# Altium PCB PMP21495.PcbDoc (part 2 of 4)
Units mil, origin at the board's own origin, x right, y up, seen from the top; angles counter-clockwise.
Board outline 10700 x 5800 mil, 6 copper layers (Top Layer, Signal Layer 3, Signal Layer 1, Signal Layer 2, Signal Layer 4, Bottom Layer), stack 66 mil thick; 305 components, 138 nets, 864 pads, 367 vias.
Unrouted connection lines stored in the file: 2.
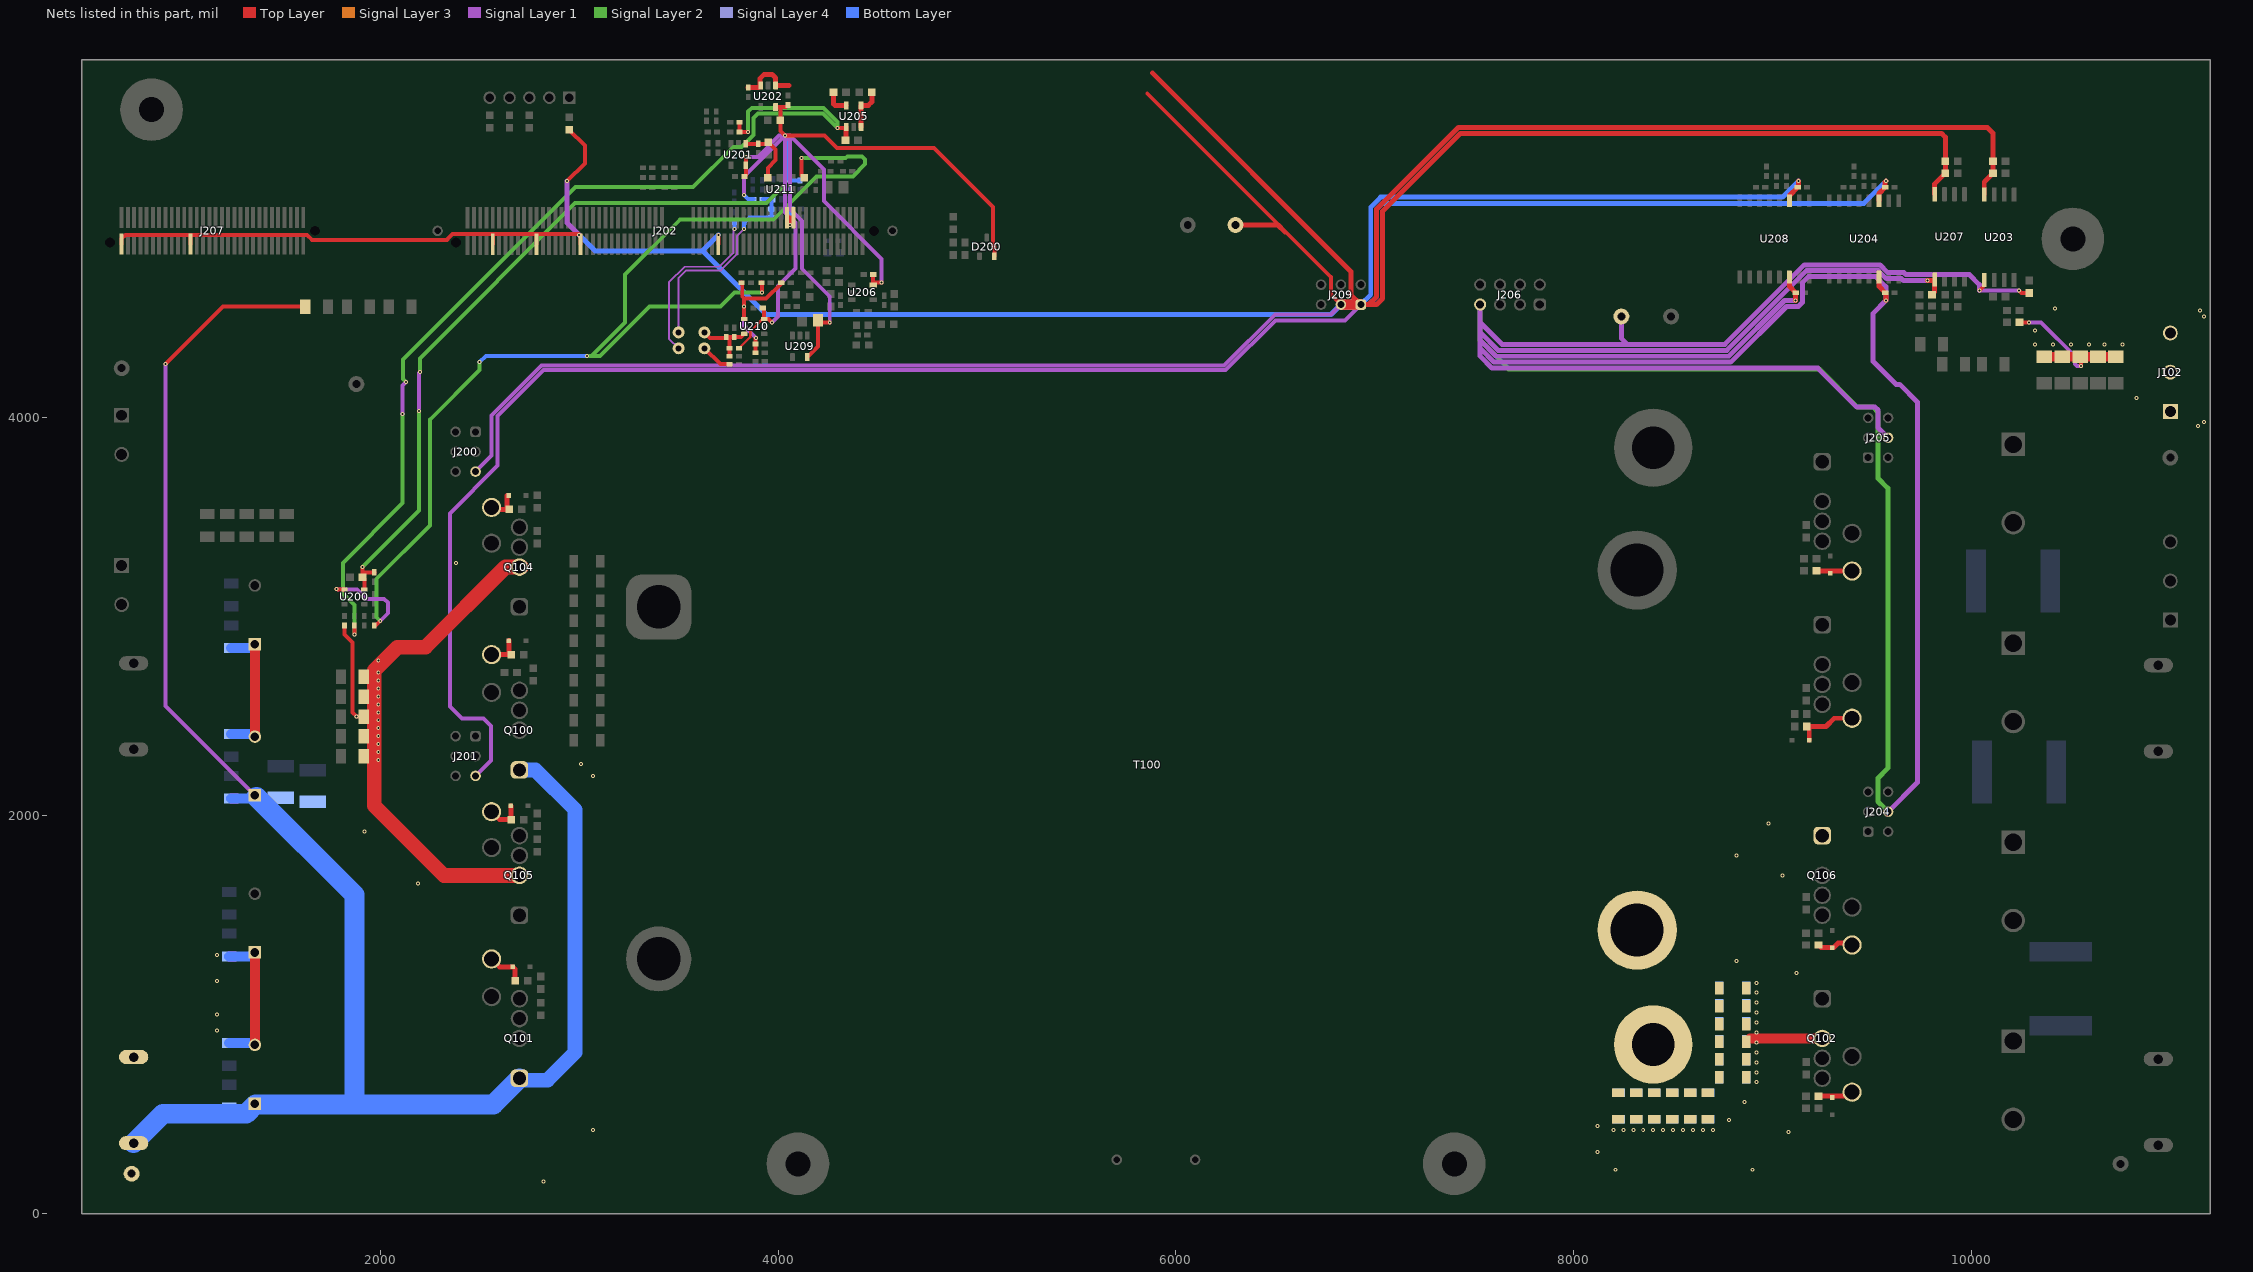
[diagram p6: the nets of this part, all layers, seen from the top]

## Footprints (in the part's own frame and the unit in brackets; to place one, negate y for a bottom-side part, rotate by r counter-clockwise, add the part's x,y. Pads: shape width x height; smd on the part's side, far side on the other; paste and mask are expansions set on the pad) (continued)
0603 [mm] "0603 from SM-752 data"
  rect 1x0.95 smd: 1(-0.8,0) 2(0.8,0)
  silkscreen extent -1.52,-0.69 1.52,0.69, body extent -0.87,-0.47 0.87,0.47, height 1
0805_HV [mil] "0805 with 30mil clearance between pads"
  rect 50x63 smd: 1(-40,0) 2(40,0)
  silkscreen extent -74,-40 74,40, body extent -43,-29 43,29, height 57
1206 [mm] "1206 from SM-752 data"
  rect 1.3x1.85 smd: 1(-1.45,0) 2(1.45,0)
  silkscreen extent -2.4,-1.21 2.4,1.21, body extent -1.7,-0.9 1.7,0.9, height 1.35
1206_190 [mm] "1206_190"
  rect 1.1x1.6 smd: 1(-1.7,0) 2(1.7,0)
  silkscreen extent -0.9,-1 0.9,1, body extent -1.75,-0.95 1.75,0.95, height 1.9
1812_254 [mm] "SMD, 2-Leads, Body 4.8x3.4mm"
  rect 1.6x3.4 smd: 1(-2,0) 2(2,0)
  silkscreen extent -0.8,-1.7 0.8,1.7, body extent -2.4,-1.7 2.4,1.7, height 2.54
B58031I_1084x785x450 [mm] "SMD, 2-Leads, Body 6.84x7.85mm"
  rect 2.5x8 smd: 1(-4.75,0) 2(4.75,0)
  silkscreen extent -3.2,-3.92 3.2,3.93, body extent -5.67,-4.17 5.67,4.18, height 4.5
CAPRD1000W60D900H1200 [mm] "Disk, Radial Capacitor"
  round 1.35 hole 0.85: 1(-5,0) 2(5,0)
  silkscreen extent -5.3,-3.5 5.3,3.5, body extent -4.48,-3.5 4.48,3.5, height 11.99
controlCARD-120HSEC [mm] "Pads are not numbered according to Samtec datasheet."
  rect 0.5x2.724 smd: 1(-23.357,-1.678) 2(-23.357,1.722) 3(-22.557,-1.678) 4(-22.557,1.722) 5(-21.757,-1.678) 6(-21.757,1.722) 7(-20.957,-1.678) 8(-20.957,1.722) 9(-20.157,-1.678) 10(-20.157,1.722) 11(-19.357,-1.678) 12(-19.357,1.722) 13(-18.557,-1.678) 14(-18.557,1.722) 15(-17.757,-1.678) 16(-17.757,1.722) 17(-16.957,-1.678) 18(-16.957,1.722) 19(-16.157,-1.678) 20(-16.157,1.722) 21(-15.357,-1.678) 22(-15.357,1.722) 23(-14.557,-1.678) 24(-14.557,1.722) 25(-13.757,-1.678) 26(-13.757,1.722) 27(-12.957,-1.678) 28(-12.957,1.722) 29(-12.157,-1.678) 30(-12.157,1.722) 31(-11.357,-1.678) 32(-11.357,1.722) 33(-10.557,-1.678) 34(-10.557,1.722) 35(-9.757,-1.678) 36(-9.757,1.722) 37(-8.957,-1.678) 38(-8.957,1.722) 39(-8.157,-1.678) 40(-8.157,1.722) 41(-7.357,-1.678) 42(-7.357,1.722) 43(-6.557,-1.678) 44(-6.557,1.722) 45(-5.757,-1.678) 46(-5.757,1.722) 47(-4.957,-1.678) 48(-4.957,1.722) 49(-4.157,-1.678) 50(-4.157,1.722) 51(-3.357,-1.678) 52(-3.357,1.722) 53(-2.557,-1.678) 54(-2.557,1.722) 55(-1.757,-1.678) 56(-1.757,1.722) 57(2.243,-1.678) 58(2.243,1.722) 59(3.043,-1.678) 60(3.043,1.722) 61(3.843,-1.678) 62(3.843,1.722) 63(4.643,-1.678) 64(4.643,1.722) 65(5.443,-1.678) 66(5.443,1.722) 67(6.243,-1.678) 68(6.243,1.722) 69(7.043,-1.678) 70(7.043,1.722) 71(7.843,-1.678) 72(7.843,1.722) 73(8.643,-1.678) 74(8.643,1.722) 75(9.443,-1.678) 76(9.443,1.722) 77(10.243,-1.678) 78(10.243,1.722) 79(11.043,-1.678) 80(11.043,1.722) 81(11.843,-1.678) 82(11.843,1.722) 83(12.643,-1.678) 84(12.643,1.722) 85(13.443,-1.678) 86(13.443,1.722) 87(14.243,-1.678) 88(14.243,1.722) 89(15.043,-1.678) 90(15.043,1.722) 91(15.843,-1.678) 92(15.843,1.722) 93(16.643,-1.678) 94(16.643,1.722) 95(17.443,-1.678) 96(17.443,1.722) 97(18.243,-1.678) 98(18.243,1.722) 99(19.043,-1.678) 100(19.043,1.722) 101(19.843,-1.678) 102(19.843,1.722) 103(20.643,-1.678) 104(20.643,1.722) 105(21.443,-1.678) 106(21.443,1.722) 107(22.243,-1.678) 108(22.243,1.722) 109(23.043,-1.678) 110(23.043,1.722) 111(23.843,-1.678) 112(23.843,1.722) 113(24.643,-1.678) 114(24.643,1.722) 115(25.443,-1.678) 116(25.443,1.722) 117(26.243,-1.678) 118(26.243,1.722) 119(27.043,-1.678) 120(27.043,1.722)
  round 0.025 hole 1.27 unplated mask+0.876: 181(-24.857,0.022) 182(28.543,1.522)
  round 1.348 hole 0.84: 185(-27.207,0.022) 186(30.893,0.022)
  silkscreen extent -32.11,-3.86 35.8,3.9, body extent -31.75,-3.48 35.3,3.52, height 12.35
controlCARD-180HSEC-60pinAddon [mm] "Pads are not numbered according to datasheet."
  round 0.025 hole 1.27 unplated mask+0.876: 61(-13.1,0) 62(13.1,1.5)
  rect 0.5x2.724 smd: 121(-11.6,-1.7) 122(-11.6,1.7) 123(-10.8,-1.7) 124(-10.8,1.7) 125(-10,-1.7) 126(-10,1.7) 127(-9.2,-1.7) 128(-9.2,1.7) 129(-8.4,-1.7) 130(-8.4,1.7) 131(-7.6,-1.7) 132(-7.6,1.7) 133(-6.8,-1.7) 134(-6.8,1.7) 135(-6,-1.7) 136(-6,1.7) 137(-5.2,-1.7) 138(-5.2,1.7) 139(-4.4,-1.7) 140(-4.4,1.7) 141(-3.6,-1.7) 142(-3.6,1.7) 143(-2.8,-1.7) 144(-2.8,1.7) 145(-2,-1.7) 146(-2,1.7) 147(-1.2,-1.7) 148(-1.2,1.7) 149(-0.4,-1.7) 150(-0.4,1.7) 151(0.4,-1.7) 152(0.4,1.7) 153(1.2,-1.7) 154(1.2,1.7) 155(2,-1.7) 156(2,1.7) 157(2.8,-1.7) 158(2.8,1.7) 159(3.6,-1.7) 160(3.6,1.7) 161(4.4,-1.7) 162(4.4,1.7) 163(5.2,-1.7) 164(5.2,1.7) 165(6,-1.7) 166(6,1.7) 167(6.8,-1.7) 168(6.8,1.7) 169(7.6,-1.7) 170(7.6,1.7) 171(8.4,-1.7) 172(8.4,1.7) 173(9.2,-1.7) 174(9.2,1.7) 175(10,-1.7) 176(10,1.7) 177(10.8,-1.7) 178(10.8,1.7) 179(11.6,-1.7) 180(11.6,1.7)
  silkscreen extent -14.68,-3.88 14.68,3.88, body extent -14.3,-3.5 14.3,3.5, height 7.95
CSNL1206 [mm] "Stackpole Electronics"
  rrect6% 1.6x2 smd: 1(-1.7,0) 2(1.7,0)
  silkscreen extent -0.63,-1.02 0.63,1.05, body extent -1.72,-0.92 1.72,0.92, height 0.9
DBV0005A_N [mm] "SOT23, 5-Leads, Body 2.9x1.6mm, Pitch 0.95mm, Lead Span 2.8mm, IPC Medium Density"
  rrect17% 1x0.6 smd: 1(-1.375,0.95) 2(-1.375,0) 3(-1.375,-0.95) 4(1.375,-0.95) 5(1.375,0.95)
  silkscreen extent -0.25,-1.55 0.25,1.55, body extent -1.42,-1.46 1.42,1.46, height 1.09
DBV0006A_L [mm] "SOT23, 6-Leads, Body 2.9x1.6mm, Pitch 0.95mm, Lead Span 2.8mm, IPC High Density"
  rrect18% 0.8x0.55 smd: 1(-1.275,0.95) 2(-1.275,0) 3(-1.275,-0.95) 4(1.275,-0.95) 5(1.275,0) 6(1.275,0.95)
  silkscreen extent -1.55,-1.53 0.55,1.53, body extent -1.42,-1.46 1.42,1.46, height 1.12
DDC0005A_N [mm]
  rrect17% 1x0.6 smd: 1(-1.375,0.95) 2(-1.375,0) 3(-1.375,-0.95) 4(1.375,-0.95) 5(1.375,0.95)
  silkscreen extent -1.25,-1.52 0.88,1.57, body extent -1.41,-1.45 1.41,1.45, height 1.1
DW0016B_HV [mm] "High voltage version of DW0016B"
  rrect17% 1.65x0.6 smd: 1(-4.875,4.445) 2(-4.875,3.175) 3(-4.875,1.905) 4(-4.875,0.635) 5(-4.875,-0.635) 6(-4.875,-1.905) 7(-4.875,-3.175) 8(-4.875,-4.445) 9(4.875,-4.445) 10(4.875,-3.175) 11(4.875,-1.905) 12(4.875,-0.635) 13(4.875,0.635) 14(4.875,1.905) 15(4.875,3.175) 16(4.875,4.445)
  silkscreen extent -5.43,-5.25 3,5.25, body extent -5.14,-5.13 5.14,5.13, height 2.5
DWV0008A [mm] "SOIC, 8-Leads, Body 5.95x7.6mm (max), Pitch 1.27mm"
  rrect17% 1.8x0.6 smd: 1(-5.45,1.905) 2(-5.45,0.635) 3(-5.45,-0.635) 4(-5.45,-1.905) 5(5.45,-1.905) 6(5.45,-0.635) 7(5.45,0.635) 8(5.45,1.905)
  silkscreen extent -6.25,-2.95 2.98,2.95, body extent -5.77,-2.92 5.77,2.93, height 2.67
Eaton_1A3400-10 [mm] "TH, 2-Leads, Body 11.1x11.94mm"
  oval 1.8x3.75 hole 1.2 slot 2.5 at 90 deg: 1(-5.5,0) 2(5.5,0)
  body extent -5.85,-6.41 5.85,6.41, height 18.03
FC_1600x4000 [mm] "TH, 2-Leads, Dia 16mm, Pin Spacing 7.5mm"
  rect 1.6x1.6 hole 1.1: 1(-3.75,0)
  round 1.6 hole 1.1: 2(3.75,0)
  silkscreen extent -8.25,-8.25 8.25,8.25, body extent -8.19,-8.24 8.23,8.24, height 42.01
FCC_disclaimer [mil]
IEC_HighVoltage_Medium [mil]
  silkscreen extent -217,-176 217,200
IEC_HotSurface_Medium [mil]
  silkscreen extent -217,-188 217,188
Keystone5000 [mil] "For Keystone 500x miniature loop terminals"
  round 80 hole 40: 1(0,0)
  silkscreen extent -52,-52 52,52, body extent -49,-49 49,49, height 182
Keystone5001 [mil] "For Keystone 500x miniature loop terminals"
  round 80 hole 40: 1(0,0)
  silkscreen extent -52,-52 52,52, body extent -49,-49 49,49, height 182
Keystone_575-4#1 [mm] "Banana Jack"
  round 10 hole 5.45: 1(0,-1.27)
  body extent -3.95,-3.95 3.92,3.93, height 2.36
Keystone_575-4#2 [mm] "Banana Jack"
  round 10 hole 5.45: 1(0,2.54)
  body extent -3.95,-3.95 3.92,3.93, height 2.36
Keystone_1902C [mil] "Hex Standoff, 4-40 threaded, nylon"
  round 1 on Mech3: 0(0,0)
  body extent -145,-126 146,126, height 501
Mill-Max_0312-0-15-15-34-27-10-0 [mm] "Pin Receptacle, .032-.046\" .075\" Dia, Gold, TH"
  round 2.45 hole 1.905: 1(0,0)
  silkscreen extent -1.52,-1.52 1.52,1.52, body extent -1.15,-1.15 1.16,1.15, height 0.46
Nichicon_2200x4500_Snap [mm]
  rrect3% 3x3 hole 2.2: 1(-5,0)
  round 3 hole 2.2: 2(5,0)
  silkscreen extent -11.6,-11.6 11.6,11.6, body extent -11.5,-11.49 11.51,11.49, height 47.01
"NY PMS 440 0025 PH" [mm] "4-40 nylon screw and mounting hole"
  round 8 hole 3.2: 1(0,0)
  body extent -3.3,-3.3 3.3,3.3, height 2.69
Payton_60518 [mm] "TH, 4-Leads, Body 130x90mm"
  rrect50% 8.325x8.325 hole 5.55: 1(-66.474,18.288)
  round 8.325 hole 5.55: 3(-66.474,-26.67)
  round 10.125 hole 6.75: 4(58.48,-22.985) 8(58.48,22.985)
  body extent -82.97,-45 65,45, height 60
Pb-Free_Overlay_Medium [mil]
  silkscreen extent -95,-95 95,95
Samtec_SSW-104-24-x-D [mm] "Receptacle, 2.54mm, 4x2, TH"
  rrect50% 1.55x1.55 hole 1.04: 1(-3.81,1.27)
  round 1.55 hole 1.04: 2(-3.81,-1.27) 3(-1.27,1.27) 4(-1.27,-1.27) 5(1.27,1.27) 6(1.27,-1.27) 7(3.81,1.27) 8(3.81,-1.27)
  silkscreen extent -5.43,-2.58 5.43,3, body extent -5.33,-2.48 5.33,2.48, height 8.51
SOD-323 [mm] "NXP recommended land pattern"
  rect 0.6x0.6 smd paste-0.05: 1(-1.1,0) 2(1.1,0)
  silkscreen extent -2.06,-0.86 1.53,0.86, body extent -1.3,-0.67 1.3,0.68, height 1.1
SOT-23 [mm] "SOT23, 3-Leads, Body 2.9x1.3mm, Pitch 0.95mm, Lead Span 2.5mm, IPC Medium Density"
  rrect50% 1x0.6 smd: 1(-1.2,0.95) 2(-1.2,-0.95) 3(1.2,0)
  silkscreen extent -1.62,-1.5 0.7,1.5, body extent -1.16,-1.45 1.21,1.45, height 1
TE_215307-3 [mm] "Receptacle, 2.54mm, 3x2, TH"
  rrect50% 1.35x1.35 hole 0.9: 1(-2.54,1.27)
  round 1.35 hole 0.9: 2(-2.54,-1.27) 3(0,1.27) 4(0,-1.27) 5(2.54,1.27) 6(2.54,-1.27)
  body extent -3.81,-2.53 3.81,2.53, height 7
TE_282856-2 [mm] "TH, 2-Leads, Body 10x10mm, Pitch 5mm"
  rect 1.9x1.9 hole 1.4: 1(-2.5,0)
  round 1.9 hole 1.4: 2(2.5,0)
  silkscreen extent -5.61,-5 5.5,5, body extent -5,-5 5.5,5, height 19
TE_282856-3 [mm] "Receptacle, 3x1, 5mm, R/A, TH"
  rect 1.9x1.9 hole 1.4: 1(-5,0)
  round 1.9 hole 1.4: 2(0,0) 3(5,0)
  silkscreen extent -8,-5 8,5, body extent -7.5,-5 8,5, height 19
TO-247-4 [mm] "FM, 4-Leads, Body 15.94x5.02mm, Pitch 2.54mm"
  rrect50% 2.24x2.24 hole 1.7: 1(-5.08,0)
  round 2.24 hole 1.7: 2(0,0) 3(2.54,0) 4(5.08,0)
  silkscreen extent -8.07,-2.49 8.07,2.72, body extent -8.07,-2.49 8.07,2.72, height 27.97
WEEE_Minimum [mil] "WEEElie bin"
  silkscreen extent -95,-172 99,104
Wurth_61300511021 [mm] "Header, 2.54 mm, 5x1, R/A, TH"
  rect 1.6x1.6 hole 1.1: 1(-5.08,0)
  round 1.6 hole 1.1: 2(-2.54,0) 3(0,0) 4(2.54,0) 5(5.08,0)
  silkscreen extent -6.75,-4.04 6.35,-1.5, body extent -6.35,-10.04 6.35,0.32, height 2.55

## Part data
C100 C105 C108 C109 C110 C113 C114 C115 C116 C117 C118 C119 C120 C121 C122 C123 C124 C125 C126 C127 C128 C129 C134 C135 C136 C137 C138 C139 C140 C141 C146 C147 C148 C149: library part CMP-0008795-2, "CAP CER 8200PF 630V NP0 1206", Cap_Case=1206, Manufacturer=TDK, PartNumber=CGA5L4NP02J822J160AA, TempCo=C0G, Tolerance_%=5%, Value1=Unknown, Value2=630V, ValueDisplayed=8200pF
C101 C102 C111 C112: library part EEU-FC2A471, "CAP ALUM 150UF 20% 400V RADIAL", Cap_Case=16x40mm, Manufacturer=Rubycon, Tolerance_%=20, Value2=400V, ValueDisplayed=150µF
C103 C104 C106 C107: library part LLS2G221MELZ, "CAP ALUM 150UF 20% 500V SNAP", Cap_Case=22x45mm, Manufacturer=Rubycon, Tolerance_%=20, Value2=500V, ValueDisplayed=150µF
C130: library part C1812W104KDRACTU, "CAP, CERM, 0.1 µF, 1000 V,+/- 10%, X7R, 1812", Cap_Case=1812, Manufacturer="Knowles Syfer", TempCo=X7R, Tolerance_%=10, Value2=1000V, ValueDisplayed=0.1µF
C131: library part C1812W104KDRACTU, "CAP CER 0.1UF 1KV X7R 1812", Cap_Case=1812, Manufacturer="Knowles Syfer", TempCo=X7R, Tolerance_%=10, Value2=1000V, ValueDisplayed=0.1µF
C132 C133 C142: library part CMP-0009311-2, "CAP, CERM, 1 uF, 500 V, +/- 20%, B58031, AEC-Q200 Grade 0, 6.84x7.85mm", Cap_Case=10.84x7.85x4.5mm, Manufacturer=TDK, Supplier Part Number 1=495-6707-ND, TempCo=B58031, Tolerance_%=20%, Value1=Unknown, Value2=500V, ValueDisplayed=1uF
C158: "CAP, CERM, 2200 pF, 250 V, +/- 20%, E, Cap, 7x12x9 mm", Cap_Case=CAPRD1000W60D900H1200, Manufacturer=MuRata, Supplier Part Number 1=490-7047-ND, TempCo=E, Tolerance_%=20, Value1=Unknown, Value2=250V, ValueDisplayed=2200pF
C200: "CAP CER 2200PF 6.3V X7R 0402", Cap_Case=0402, Manufacturer=MuRata, Supplier Part Number 1=GRM155R60J222KA01D-ND, TempCo=X5R, Tolerance_%=10, Value2=6.3V, ValueDisplayed=2200pF
C201 C211 C225 C227 C230 C231: library part 06033C104JAT2A, "CAP, CERM, 0.1uF, 25V, +/-5%, X7R, 0603", Cap_Case=0603, Manufacturer=MuRata, Supplier Part Number 1=490-8015-1-ND, TempCo=X7R, Tolerance_%=10, Value2=16V, ValueDisplayed=0.1µF
C202 C205 C240: "CAP, CERM, 0.1uF, 25V, +/-5%, X7R, 0603", Cap_Case=0603, Manufacturer=AVX, Supplier Part Number 1=478-3713-1-ND, TempCo=X7R, Tolerance_%=5, Value1="0.05 ohm", Value2=25V, ValueDisplayed=0.1µF
C203 C206 C207: "CAP, CERM, 470 pF, 50 V,+/- 10%, X7R, AEC-Q200 Grade 1, 0402", Cap_Case=0402, Manufacturer=TDK, Supplier Part Number 1=445-6888-1-ND, TempCo=X7R, Tolerance_%=10, Value1="4.96489 ohm", Value2=50V, ValueDisplayed=470pF
C204: "CAP, CERM, 10 pF, 50 V,+/- 5%, C0G/NP0, 0603", Cap_Case=0603, Manufacturer=Kemet, Supplier Part Number 1=399-1049-1-ND, TempCo=C0G/NP0, Tolerance_%=5, Value2=50V, ValueDisplayed=10pF
C208 C216 C217 C221 C229 C232: "CAP, CERM, 0.01 µF, 10 V,+/- 10%, X5R, 0402", Cap_Case=0402, Manufacturer=MuRata, Supplier Part Number 1=GRM155R61A103KA01D-ND, TempCo=X5R, Tolerance_%=10, Value2=10V, ValueDisplayed=0.01µF
C209 C218 C223: "CAP, CERM, 1uF, 25V, +/-10%, X7R, 0603", Cap_Case=0603, Manufacturer=TDK, Supplier Part Number 1=445-5956-1-ND, TempCo=X7R, Tolerance_%=10, Value1=Unknown, Value2=25V, ValueDisplayed=1uF
C210 C224: "CAP, CERM, 4.7 µF, 10 V,+/- 10%, X5R, 0603", Cap_Case=0603, Manufacturer=TDK, Supplier Part Number 1=445-7482-1-ND, TempCo=X5R, Tolerance_%=10, Value2=10V, ValueDisplayed=4.7µF
C212 C213 C214 C219 C226 C233 C241: "CAP, CERM, 0.1 µF, 25 V,+/- 20%, X7R, 0402", Cap_Case=0402, Manufacturer=TDK, Supplier Part Number 1=445-7349-1-ND, TempCo=X7R, Tolerance_%=20, Value2=25V, ValueDisplayed=0.1µF
C215 C228: "CAP, CERM, 0.01 µF, 100 V,+/- 10%, X7R, 0603", Cap_Case=0603, Manufacturer=AVX, Supplier Part Number 1=478-1205-1-ND, TempCo=X7R, Tolerance_%=10, Value1="0.098 ohm", Value2=100V, ValueDisplayed=0.01µF
C220 C222: "CAP, CERM, 0.1uF, 6.3V, +/-10%, X7R, 0402", Cap_Case=0402, Manufacturer=MuRata, Supplier Part Number 1=GRM155R70J104KA01D-ND, TempCo=X7R, Tolerance_%=10, Value1=Unknown, Value2=6.3V, ValueDisplayed=0.1uF
C234 C235 C236 C237: library part CMP-0085851-1, "CAP, CERM, 22 pF, 50 V,+/- 5%, C0G/NP0, 0402", Cap_Case=0402, Manufacturer=MuRata, Supplier Part Number 1=490-8589-1-ND, TempCo=C0G/NP0, Tolerance_%=1, Value2=50V, ValueDisplayed=22pF
C238: "CAP, CERM, 2.2 µF, 6.3 V,+/- 10%, X6S, 0603", Cap_Case=0603, Manufacturer=MuRata, Supplier Part Number 1=GRM188C80J225KE19D-ND, TempCo=X6S, Tolerance_%=10, Value2=6.3V, ValueDisplayed=2.2µF
C239: "CAP, CERM, 220 pF, 50 V,+/- 5%, C0G/NP0, 0402", Cap_Case=0402, Manufacturer=MuRata, Supplier Part Number 1=490-1293-1-ND, TempCo=C0G/NP0, Tolerance_%=5, Value2=50V, ValueDisplayed=220pF
C242 C244 C245 C254: "CAP, CERM, 10 pF, 10 V,+/- 2.5%, C0G/NP0, 0402", Cap_Case=0402, Manufacturer=Kemet, Supplier Part Number 1=399-8939-1-ND, TempCo=C0G/NP0, Tolerance_%=2.5, Value2=10V, ValueDisplayed=10pF
C243: "CAP, CERM, 0.1 µF, 25 V,+/- 5%, X7R, 0805", Cap_Case=0805, Manufacturer=AVX, Supplier Part Number 1=478-7946-1-ND, TempCo=X7R, Tolerance_%=5, Value2=25V, ValueDisplayed=0.1µF
C246 C250: "CAP, CERM, 2.2 pF, 50 V,+/- 5%, C0G/NP0, 0402", Cap_Case=0402, Manufacturer=MuRata, Supplier Part Number 1=490-6227-1-ND, TempCo=C0G/NP0, Tolerance_%=5, Value2=50V, ValueDisplayed=2.2pF
C247 C249 C251 C253: "CAP, CERM, 0.1 µF, 16 V,+/- 10%, X7R, 0402", Cap_Case=0402, Manufacturer=AVX, Supplier Part Number 1=478-7888-1-ND, TempCo=X7R, Tolerance_%=10, Value2=16V, ValueDisplayed=0.1µF
C248 C252: "CAP, CERM, 2200 pF, 50 V,+/- 10%, X7R, AEC-Q200 Grade 1, 0402", Cap_Case=0402, Manufacturer=TDK, Supplier Part Number 1=445-5606-1-ND, TempCo=X7R, Tolerance_%=10, Value1="1.07794 ohm", Value2=50V, ValueDisplayed=2200pF
D100 D101 D102 D103 D104 D105 D106 D107: "Diode, Schottky, 40 V, 0.5 A, SOD-323", Manufacturer=Toshiba, Supplier Part Number 1=CUS05S40H3FCT-ND, Value1=0.5A, Value2=0.6V
D200: library part CMP-0028456-1, "Diode, Schottky, 30 V, 0.2 A, SOT-23", Manufacturer="Diodes Inc.", Supplier Part Number 1=BAT54S-FDICT-ND, Value1=0.2A, Value2=0.65V
H200 H201 H202 H203: library part CMP-0003617-1, "Machine Screw, Round, #4-40 x 1/4, Nylon, Philips panhead", Manufacturer="B&F Fastener Supply", Supplier Part Number 1=H542-ND
H204 H205 H206 H207: library part CMP-0003610-1, "Standoff, Hex, 0.5\"L #4-40 Nylon", Manufacturer=Keystone, Supplier Part Number 1=36-1902C-ND
J100 J103: library part CMP-0054978-1, "Therminal Block, 5 mm, 2-pole, Tin, TH", Manufacturer="TE Connectivity", Supplier Part Number 1=A98355-ND
J101 J102: library part CMP-0054983-1, "Receptacle, 3x1, 5mm, R/A, TH", Color=Green, Current_A=24A, Manufacturer="TE Connectivity", Supplier Part Number 1=A98356-ND, Voltage_V=300V
J104 J105: library part CMP-0055165-2, "Standard Banana Jack, Uninsulated, 5.5mm", Manufacturer=Keystone, Supplier Part Number 1=36-575-4-ND
J200 J201 J204 J205 J209: library part CMP-0082603-1, "Receptacle, 2.54mm, 3x2, Tin, TH", Color=Green, Manufacturer="TE Connectivity", Supplier Part Number 1=A106656-ND
J202: library part controlCARD-120HSEC, "C2000 controlCARD-120HSEC connector, SMT", Manufacturer=Samtec
J203: library part CMP-0054800-1, "Header, 2.54 mm, 5x1, Gold, R/A, TH", Color=Black, Manufacturer="Wurth Elektronik", Supplier Part Number 1=732-5338-ND
J206: library part CMP-0055706-1, "Receptacle, 2.54mm, 4x2, Gold, TH", Color=Black, Current_A=4.7A, Manufacturer=Samtec, Voltage_V=465V
J207: library part CMP-0003859-2, "C2000 controlCARD-180HSEC (60-pin addon) connector, SMT", Manufacturer=Samtec
Logo2: library part CMP-0074839-1
Logo3: library part CMP-0074847-1, "FCC_disclaimer"
Logo4: library part CMP-0074769-1
LOGO100: library part IEC_HotSurface, "IEC 61010-1 Hot Surface Warning"
LOGO101 LOGO102 LOGO104: library part IEC_HighVoltage, "IEC 61010-1 High Voltage Warning"
Q100 Q101 Q102 Q103 Q104 Q105 Q106 Q107: library part CMP-0067575-2, "ZFET 900V, 30 MOHM, G3 SIC MOSFE", Alternate Manufacturer=None, Manufacturer=Cree
R100 R101 R105 R106 R110 R111 R114 R115: "RES, 1.00 M, 1%, 0.25 W, 1206", Manufacturer=Vishay-Dale, Power_W=0.25, Supplier Part Number 1=541-1.00MFCT-ND, TempCo="100 ppm/C", Tolerance_%=1, Value1=1%, Value2=0.25W, Value_Code=1M00, ValueDisplayed=1.00M
R102 R104 R108 R112 R116: library part CSNL1206FT5L00, "RES 0.006 OHM 1% 1W 1206", Manufacturer="Vishay Dale", Power_W=1, TempCo="50 ppm/C", Value1=1%, Value2=1W, ValueDisplayed=0.006
R103 R107 R109 R113 R117 R142 R143 R144 R145 R146: library part CMP-0018570-2, "RES, 0.01, 1%, 1 W, 1206", Manufacturer=Vishay-Dale, Power_W=1W, Supplier Part Number 1=WSLP-.01CT-ND, TempCo="75 ppm/C", Tolerance_%=1%, Value_Code=R010, ValueDisplayed=0.01
R118 R119 R120 R121 R130 R131 R132 R133: "RES, 5.11, 1%, 0.1 W, 0603", Manufacturer=Vishay-Dale, Power_W=0.1, Supplier Part Number 1=541-5.11HHCT-ND, TempCo="100 ppm/C", Tolerance_%=1, Value1=1%, Value2=0.1W, Value_Code=5R11, ValueDisplayed=5.11
R122 R123 R124 R125 R134 R135 R136 R137: "RES, 1.00, 1%, 0.1 W, 0603", Manufacturer="Yageo America", Power_W=0.1, Supplier Part Number 1=311-1.00HRCT-ND, TempCo="200 ppm/C", Tolerance_%=1, Value1=1%, Value2=0.1W, Value_Code=1R00, ValueDisplayed=1.00
R126 R127 R128 R129 R138 R139 R140 R141: "RES, 10.0 k, 1%, 0.1 W, 0603", Manufacturer=Vishay-Dale, Power_W=0.1, Supplier Part Number 1=541-10.0KHCT-ND, TempCo="100 ppm/C", Tolerance_%=1, Value1=1%, Value2=0.1W, Value_Code=10k0, ValueDisplayed=10.0k
R200 R201 R219 R220: "RES, 0, 5%, 0.063 W, 0402", Manufacturer=Vishay-Dale, Power_W=0.063, Supplier Part Number 1=541-0.0JCT-ND, TempCo="200 ppm/C", Tolerance_%=5, Value1=5%, Value2=0.063W, Value_Code=0000, ValueDisplayed=0
R202 R205 R210: library part CMP-0016927-3, "RES, 365 k, 1%, 0.25 W, AEC-Q200 Grade 0, 1206", Manufacturer=Vishay-Dale, Power_W=250mW, Supplier Part Number 1=541-365KFCT-ND, TempCo="100 ppm/C", Tolerance_%=1%, Value2=0.25W, Value_Code=365k
R203 R207 R229 R253 R254 R264: "RES SMD 56.2 OHM 1% 1/16W 0402", Manufacturer=Vishay-Dale, Power_W=0.063, Supplier Part Number 1=541-56.2LCT-ND, TempCo="100 ppm/C", Tolerance_%=1, Value1=1%, Value2=0.063W, Value_Code=56R2, ValueDisplayed=56.2
R204 R215: library part CRCW0402150KFKED, "RES, 150 k, 1%, 0.063 W, 0402", Manufacturer=Panasonic, Power_W=100mW, Supplier Part Number 1=P240KLCT-ND, TempCo="100 ppm/C", Tolerance_%=1%, Value2=0.1W, Value_Code=240k
R206: "RES, 28.7 k, 1%, 0.125 W, 0805", Manufacturer=Vishay-Dale, Power_W=0.125, Supplier Part Number 1=541-28.7KCCT-ND, TempCo="100 ppm/C", Tolerance_%=1, Value1=1%, Value2=0.125W, Value_Code=28k7, ValueDisplayed=28.7k
R208 R213 R216 R217 R256 R259 R261 R265: "RES, 10.0 k, 1%, 0.063 W, 0402", Manufacturer=Vishay-Dale, Power_W=0.063, Supplier Part Number 1=541-10.0KLCT-ND, TempCo="100 ppm/C", Tolerance_%=1, Value1=1%, Value2=0.063W, Value_Code=10k0, ValueDisplayed=10.0k
R209 R218: library part CMP-0022243-4, "RES, 25.5, 1%, 0.1 W, AEC-Q200 Grade 0, 0603", Manufacturer=Vishay-Dale, Power_W=100mW, Supplier Part Number 1=541-25.5HCT-ND, TempCo="100 ppm/C", Tolerance_%=1%, Value2=0.1W, Value_Code=25R5, ValueDisplayed=25.5
R211: "RES, 1.24 k, 1%, 0.063 W, 0402", Manufacturer=Vishay-Dale, Power_W=0.063, Supplier Part Number 1=541-1.24KLCT-ND, TempCo="100 ppm/C", Tolerance_%=1, Value1=1%, Value2=0.063W, Value_Code=1k24, ValueDisplayed=1.24k
R212: "RES, 56.2, 1%, 0.1 W, 0603", Manufacturer=Vishay-Dale, Power_W=0.1, Supplier Part Number 1=541-56.2HCT-ND, TempCo="100 ppm/C", Tolerance_%=1, Value1=1%, Value2=0.1W, Value_Code=56R2, ValueDisplayed=56.2
R214: library part CMP-0022512-4, "RES, 5.49 k, 1%, 0.1 W, AEC-Q200 Grade 0, 0603", Manufacturer=Vishay-Dale, Power_W=100mW, Supplier Part Number 1=541-5.49KHCT-ND, TempCo="100 ppm/C", Tolerance_%=1%, Value2=0.1W, Value_Code=5k49, ValueDisplayed=5.49k
R221 R222: "RES, 4.99 k, 1%, 0.063 W, 0402", Manufacturer=Vishay-Dale, Power_W=0.063, Supplier Part Number 1=541-4.99KLCT-ND, TempCo="100 ppm/C", Tolerance_%=1, Value1=1%, Value2=0.063W, Value_Code=4k99, ValueDisplayed=4.99k
R223 R224: "RES, 9.31 k, 1%, 0.063 W, 0402", Manufacturer=Vishay-Dale, Power_W=0.063, Supplier Part Number 1=541-9.31KLCT-ND, TempCo="100 ppm/C", Tolerance_%=1, Value1=1%, Value2=0.063W, Value_Code=9k31, ValueDisplayed=9.31k
R225: library part CMP-0022599-4, "RES, 7.15 k, 1%, 0.1 W, AEC-Q200 Grade 0, 0603", Manufacturer=Vishay-Dale, Power_W=100mW, Supplier Part Number 1=541-7.15KHCT-ND, TempCo="100 ppm/C", Tolerance_%=1%, Value2=0.1W, Value_Code=7k15, ValueDisplayed=7.15k
R226: "RES, 14.3 k, 1%, 0.1 W, 0603", Manufacturer=Vishay-Dale, Power_W=0.1, Supplier Part Number 1=541-14.3KHCT-ND, TempCo="100 ppm/C", Tolerance_%=1, Value1=1%, Value2=0.1W, Value_Code=14k3, ValueDisplayed=14.3k
R227: "RES, 1.00 k, 1%, 0.1 W, 0603", Manufacturer=Vishay-Dale, Power_W=0.1, Supplier Part Number 1=541-1.00KHCT-ND, TempCo="100 ppm/C", Tolerance_%=1, Value1=1%, Value2=0.1W, Value_Code=1k00, ValueDisplayed=1.00k
R228: "RES, 25.5, 1%, 0.1 W, 0603", Manufacturer=Vishay-Dale, Power_W=0.1, Supplier Part Number 1=541-25.5HCT-ND, TempCo="100 ppm/C", Tolerance_%=1, Value1=1%, Value2=0.1W, Value_Code=25R5, ValueDisplayed=25.5
R230 R235: "RES, 39.2, 1%, 0.1 W, 0603", Manufacturer=Vishay-Dale, Power_W=0.1, Supplier Part Number 1=541-39.2HCT-ND, TempCo="100 ppm/C", Tolerance_%=1, Value1=1%, Value2=0.1W, Value_Code=39R2, ValueDisplayed=39.2
R231 R232 R233 R234: library part CMP-0026739-1, "RES, 4.70 k, 1%, 0.0625 W, 0402", Manufacturer="TE Connectivity", Power_W=0.063, Supplier Part Number 1=A121542CT-ND, TempCo="100 ppm/C", Tolerance_%=1, Value1=1%, Value2=0.063W, Value_Code=4k70, ValueDisplayed=4.70k
R236: "RES, 7.15 k, 1%, 0.063 W, 0402", Manufacturer=Vishay-Dale, Power_W=0.063, Supplier Part Number 1=541-7.15KLCT-ND, TempCo="100 ppm/C", Tolerance_%=1, Value1=1%, Value2=0.063W, Value_Code=7k15, ValueDisplayed=7.15k
R237 R239 R240: "RES, 2.00 M, 1%, 0.25 W, 1206", Manufacturer="Yageo America", Power_W=0.25, Supplier Part Number 1=311-2.00MFRCT-ND, TempCo="100 ppm/C", Tolerance_%=1, Value1=1%, Value2=0.25W, Value_Code=2M00, ValueDisplayed=2.00M
R238 R248: library part CMP-0022635-4, "RES, 8.25 k, 1%, 0.1 W, AEC-Q200 Grade 0, 0603", Manufacturer=Vishay-Dale, Power_W=100mW, Supplier Part Number 1=541-8.25KHCT-ND, TempCo="100 ppm/C", Tolerance_%=1%, Value2=0.1W, Value_Code=8k25, ValueDisplayed=8.25k
R241 R247 R249 R250 R251 R252: "RES, 0, 5%, 0.1 W, 0603", Manufacturer=Vishay-Dale, Power_W=0.1, Supplier Part Number 1=541-0.0GCT-ND, TempCo="200 ppm/C", Tolerance_%=5, Value1=5%, Value2=0.1W, Value_Code=0000, ValueDisplayed=0
R242 R243 R244 R245: library part CMP-0022278-4, "RES, 2.55 k, 1%, 0.1 W, AEC-Q200 Grade 0, 0603", Manufacturer=Vishay-Dale, Power_W=100mW, Supplier Part Number 1=541-2.55KHCT-ND, TempCo="100 ppm/C", Tolerance_%=1%, Value2=0.1W, Value_Code=2k55, ValueDisplayed=2.55k
R246: library part CMP-0022242-4, "RES, 25.5 k, 1%, 0.1 W, AEC-Q200 Grade 0, 0603", Manufacturer=Vishay-Dale, Power_W=100mW, Supplier Part Number 1=541-25.5KHCT-ND, TempCo="100 ppm/C", Tolerance_%=1%, Value2=0.1W, Value_Code=25k5, ValueDisplayed=25.5k
R255 R260: "RES, 3.65 k, 1%, 0.063 W, 0402", Manufacturer=Vishay-Dale, Power_W=0.063, Supplier Part Number 1=541-3.65KLCT-ND, TempCo="100 ppm/C", Tolerance_%=1, Value1=1%, Value2=0.063W, Value_Code=3k65, ValueDisplayed=3.65k
R257 R262: "RES, 1.00 k, 1%, 0.063 W, 0402", Manufacturer=Vishay-Dale, Power_W=0.063, Supplier Part Number 1=541-1.00KLCT-ND, TempCo="100 ppm/C", Tolerance_%=1, Value1=1%, Value2=0.063W, Value_Code=1k00, ValueDisplayed=1.00k
R258 R263: library part CRCW04021K00FKED, "RES, 1.00 k, 1%, 0.063 W, 0402", Manufacturer=Vishay-Dale, Power_W=0.063, Supplier Part Number 1=541-10.0KLCT-ND, TempCo="100 ppm/C", Tolerance_%=1, Value1=1%, Value2=0.063W, Value_Code=10k0, ValueDisplayed=10.0k
T100: library part CMP-0081898-1, "Transformer, 25 uH, TH", Manufacturer=Payton, ValueDisplayed=25µH
TP100 TP101 TP109: "Test Point, Miniature, Red, TH", Color=Red, Manufacturer=Keystone, Supplier Part Number 1=36-5000-ND
TP102 TP103 TP105 TP106 TP107: "Test Point, Miniature, Black, TH", Color=Black, Manufacturer=Keystone, Supplier Part Number 1=36-5001-ND
TP108: library part 5000, "Test Point, Miniature, Red, TH", Color=Black, Manufacturer=Keystone, Supplier Part Number 1=36-5001-ND
TP200 TP201 TP202 TP203 TP204 TP205 TP206 TP207 TP208 TP209 TP210 TP211 TP212 TP213 TP214 TP215: library part 0312-0-15-15-34-27-10-0, "Pin Receptacle, .032-.046\" .075\" Dia, Gold, TH", Manufacturer=Mill-Max, Supplier Part Number 1=0312-015153427100-ND
U200 U210 U211: library part CMP-0040149-1, "IC OPAMP VFB 45MHZ RRO SOT23-5", Manufacturer="Texas Instruments", PartNumber=LMV116MF
U201 U206 U209: library part CMP-0040888-1, "Precision, 20 MHz, 0.9 pA Ib, RRIO, CMOS Operational Amplifier, 1.8 to 5.5 V, -40 to 125 degC, 5-pin SOT23 (DBV5), Green (RoHS & no Sb/Br)", Manufacturer="Texas Instruments", Total Supply Voltage(Max)(+5V is 5, +/-5V is 10)=5.5, Total Supply Voltage(Min)(+5V is 5, +/-5V is 10)=1.8
U202: "Capacitor-Free, 150-mA, Low-Dropout Regulator with Foldback Current Limit for Portable Devices, DBV0005A", Alternate Manufacturer="Texas Instruments"
U203: library part CMP-0080587-1, "Precision Reinforced Isolated Amplifier for Current Sensing, DWV0008A (SOIC-8)", Alternate Manufacturer="Texas Instruments"
U204 U208: library part CMP-0076069-2, "High-Immunity, 5.7kVRMS Reinforced Dual-Channel 2/0 Digital Isolator, 100Mbps, DW0016B (SOIC-16)", Alternate Manufacturer="Texas Instruments", Alternate PartNumber=ISO7820FDW
U205: library part CMP-0066190-1, "Low-Drift, Low-Power, Dual-Output VREF and VREF/2 Voltage Reference, DDC0005A (SOT-23-T-5)", Alternate Manufacturer="Texas Instruments", Alternate PartNumber=REF2033AIDDCT
U207: library part CMP-0078341-1, "Precision, 2-V Input, Reinforced Isolated Amplifier, DWV0008A (SOIC-8)", Alternate Manufacturer="Texas Instruments", Alternate PartNumber=AMC1311BDWV
XF100 XF101 XF102 XF103: library part CMP-0082116-2, "FUSE CLIP CARTRIDGE 30A PCB", Manufacturer=Eaton, Supplier Part Number 1=1A3400-10-ND

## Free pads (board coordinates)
  round 60 hole 30: 1(3630,4350) 2(3630,4430) 3(3500,4350) 4(3500,4430)

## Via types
v1: diameter 20, hole 10, Top Layer to Bottom Layer, 367 vias

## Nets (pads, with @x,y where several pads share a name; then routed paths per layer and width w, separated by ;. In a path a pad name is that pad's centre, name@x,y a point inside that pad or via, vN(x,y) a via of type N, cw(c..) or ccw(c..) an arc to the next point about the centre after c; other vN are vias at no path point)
1V65: C217.2 C231.1 R215.1 R236.1 U205.1 | length 5183.6
  Top Layer w20: v1(1870,2910) R215.1@1870,2956.38 ; C217.2@3806.49,5487.13 R236.1@3806.49,5437.13 v1(3850,5437.13) ; v1(4300,5457.13) U205.1@4336.73,5457.13
  Top Layer w25: C231.1@4342.6,5401.22 U205.1@4342.6,5462.99
  Signal Layer 1 w20: v1(2112.13,4020) 2112.13,4162.13 v1(2130,4180)
  Signal Layer 2 w20: v1(1870,2910) 1870,3059.98 1823.17,3106.81 1823.17,3107.41 1812.13,3118.45 1812.13,3271.55 2112.13,3571.55 v1(2112.13,4020) ; v1(2130,4180) 2114.87,4195.13 2114.87,4294.06 2980.81,5160 3572.87,5160 3774.85,5361.98 3816.85,5361.98 3877.72,5422.84 3877.72,5507.72 3900,5530 4227.13,5530 v1(4300,5457.13) 4300,5488.45 4229.2,5559.25 3867.92,5559.25 3850,5541.33 v1(3850,5437.13)
3V3: C201.1 C212.1 C218.2 C220.1 C226.1 C243.1 C247.1 C251.1 D200.2 R208.2 R256.2 R261.2 U200.6 U201.5 U202.5 U206.5 U209.5 U210.6 U211.6 | length 10128
  Top Layer w12: R256.2@3803.62,4350 3860,4406.38 3860,4434.86 3922.54,4497.4 U210.6@3930.2,4497.4
  Top Layer w20: C201.1@1910,3201.5 v1(1910,3250) ; 1912.13,3223.62 R208.2@1970,3223.62 ; U200.6@1920.2,3137.4 C201.1@1920.2,3191.3 ; C212.1@3838.35,5221.66 U201.5@3838.35,5270.12 v1(3838.35,5312.76) ; C247.1@3930.2,4546.3 U210.6@3930.2,4497.4 3952.6,4497.4 v1(3970,4480) ; U202.5@3987.4,5562.99 4039.49,5562.99 C220.1@4050,5573.5 ; 4011.5,5561.04 C218.2@4011.5,5497.13 4011.5,5443.22 v1(4035.59,5419.12) 4232.61,5419.12 4295.59,5356.14 4783.86,5356.14 5080,5060 5080,4870 5087.4,4862.6 D200.2@5087.4,4812.76 ; U209.5@4147.4,4305.87 4200,4358.46 C243.1@4200,4490 ; C243.1@4210,4480 v1(4260,4480) ; C226.1@4478.54,4720.47 4478.54,4680 v1(4520,4680)
  Signal Layer 1 w20: v1(2193.88,4033.88) 2193.88,4225.83 v1(2199.03,4230.97) ; v1(3830,5120) 3830,5213.53 v1(4035.59,5419.12) ; v1(3838.35,5312.76) 3898.97,5312.76 4005.33,5419.12 v1(4035.59,5419.12) ; v1(3970,4480) 4000.02,4510.02 4000.02,4664.27 4087.87,4752.13 4087.87,4981.55 4035.59,5033.83 v1(4035.59,5419.12) ; v1(4260,4480) 4260,4610 4120,4750 4120,4990 4060,5050 4060,5394.71 v1(4035.59,5419.12) ; v1(4520,4680) 4520,4800 4230,5090 4230,5250 4060.88,5419.12 v1(4035.59,5419.12)
  Signal Layer 2 w20: v1(1910,3250) 2193.88,3533.88 v1(2193.88,4033.88) ; v1(2199.03,4230.97) 2199.03,4299.38 2979.65,5080 3941.74,5080 4035.59,5173.85 v1(4035.59,5419.12)
  Bottom Layer w20: v1(3830,5120) 3850,5100 R261.2@3876.38,5100 ; v1(4035.59,5419.12) 4051.85,5402.86 U211.6@4051.85,5200.2 4058.43,5193.62 C251.1@4110,5193.62
3V3ref: C230.1 U205.5 | length 125.6
  Top Layer w25: C230.1@4278.5,5637.13 4278.5,5578.62 4285.87,5571.26 U205.5@4342.6,5571.26
5Vp: C210.1 C211.1 C213.1 C219.1 C222.1 C224.1 C225.1 C227.1 J200.5 J201.5 J202.48 J202.84 J202.98 J202.112 J207.158 J207.180 J209.1 J209.3 R252.2 TP109.1 U202.1 U202.3 U203.8 U204.3 U205.3 U205.4 U207.8 U208.3 | length 37336.4
  Top Layer w20: J207.180@699.57,4874.05 699.57,4901.3 718.27,4920 1632.36,4920 1656.65,4895.71 2335.71,4895.71 2337.79,4897.79 2337.79,4898.82 2362.91,4923.94 2996.06,4923.94 v1(3000,4920) 3006.65,4913.35 J202.84@3006.65,4873.19 ; J207.158@1046.02,4874.05 J207.158@1046.02,4916.02 ; J202.112@2565.71,4873.19 J202.112@2565.71,4913.59 ; J202.98@2786.18,4873.19 J202.98@2786.18,4913.82 ; v1(2940,5190) 3030,5280 3030,5368.5 R252.2@2950,5448.5 ; J202.48@3699.57,4873.19 3699.57,4919.57 v1(3700,4920) ; 5856.33,5630.98 6780,4707.31 6780,4620 J209.3@6830,4570
  Top Layer w25: C222.1@3850,5660.75 3902.09,5660.75 3910,5668.66 3910,5707.13 3930,5727.13 3970,5727.13 3987.4,5709.72 U202.1@3987.4,5671.26 4054.02,5671.26 ; U205.3@4417.4,5462.99 U205.4@4417.4,5571.26 4454.13,5571.26 4471.5,5588.62 C227.1@4471.5,5637.13 ; 5881.89,5734.6 6880,4736.49 6880,4620 J209.1@6930,4570 6970,4570 ; TP109.1@6300,4970 6513.77,4970 6548.23,4935.54 ; U208.3@9085,5091.93 9085,5118.62 C213.1@9126.38,5160 9130,5163.62 v1(9130,5190) ; U204.3@9535,5091.93 9535,5128.62 C219.1@9566.38,5160 9566.38,5186.38 v1(9570,5190) ; U207.8@9815,5124.57 9815,5176.5 C225.1@9868.5,5230 C224.1@9868.5,5290 9868.5,5411.5 9850,5430 7430,5430 7040,5040 7040,4600 7010,4570 6970,4570 ; U203.8@10064.49,5122.6 10064.49,5185.98 C211.1@10108.5,5230 C210.1@10108.5,5290 10108.5,5431.5 10080,5460 7420,5460 7010,5050 7010,4610 6970,4570
  Top Layer w50: J209.3@6830,4570 J209.1@6930,4570
  Signal Layer 1 w20: J200.5@2470,3730 J200.5@2470,3740 ; J201.5@2479,2200 2556.46,2277.46 2556.46,2451.55 2520.13,2487.87 2411.55,2487.87 2350,2549.42 2350,3520 2590,3760 2590,4010 2820,4240 6250,4240 6500,4490 6850,4490 J209.1@6930,4570 ; J200.5@2479,3730 2560,3811 2560,4011.56 2810.88,4262.44 6241.86,4262.44 6499.84,4520.42 6780.42,4520.42 J209.3@6830,4570
  Signal Layer 1 w25: v1(2940,5190) 2940,4980 v1(3000,4920)
  Signal Layer 1 w50: J209.3@6830,4570 J209.1@6930,4570
  Signal Layer 2 w50: J209.3@6830,4570 J209.1@6930,4570
  Signal Layer 3 w50: J209.3@6830,4570 J209.1@6930,4570
  Signal Layer 4 w50: J209.3@6830,4570 J209.1@6930,4570
  Bottom Layer w25: v1(3000,4920) 3080,4840 3620,4840 ; v1(3700,4920) 3620,4840 ; J209.3@6830,4570 6780,4520 3940,4520 3620,4840 ; v1(9130,5190) 9050,5110 8903.74,5110 8903.37,5109.63 8878.21,5109.63 8877.83,5110 7030,5110 6980,5060 6980,4620 J209.1@6930,4570 6970,4570 7010,4610 7010,5050 7039.13,5079.13 9459.13,5079.13 v1(9570,5190)
  Bottom Layer w50: J209.3@6830,4570 J209.1@6930,4570
5Vs: C209.2 C214.1 C223.2 C233.1 J204.4 J205.4 J206.7 TP108.1 U203.1 U204.14 U207.1 U208.14 | length 19946.4
  Top Layer w20: v1(10040,4640) 10064.49,4664.49 U203.1@10064.49,4693.46 ; v1(10240,4640) 10251.5,4628.5 C209.2@10290,4628.5
  Top Layer w25: U208.14@9085,4708.07 9085,4661.38 C233.1@9116.38,4630 v1(9116.38,4590) ; U204.14@9535,4708.07 9535,4661.38 C214.1@9566.38,4630 9570,4626.38 v1(9570,4590) ; v1(9780,4690) 9809.57,4690 U207.1@9815,4695.43 9815,4633.5 C223.2@9801.5,4620
  Signal Layer 1 w20: v1(10040,4640) v1(10240,4640)
  Signal Layer 1 w25: J206.7@7530,4570 7530,4480 ; TP108.1@8240,4510 8240,4400 8270,4370 ; v1(9116.38,4590) 9060,4590 8780,4310 7610,4310 7530,4390 ; J204.4@9581,2020 9728.62,2167.62 9728.62,4079.25 9639.25,4168.62 9620.85,4168.62 9505.75,4283.72 9505.75,4525.75 v1(9570,4590) 9570,4660 9520,4710 9180,4710 9150,4680 9150,4580 9130,4560 9070,4560 8790,4280 7600,4280 7530,4350 ; J205.4@9581,3900 9530,3951 9530,4040 9516.05,4053.95 9423.95,4053.95 9227.91,4250 7590,4250 7530,4310 7530,4350 ; v1(9780,4690) 9779.63,4690.37 9657.96,4690.37 9647.96,4700.37 9571.71,4700.37 9532.09,4740 9170,4740 8770,4340 7620,4340 7530,4430 ; v1(10040,4640) 10040,4670 9990,4720 9670,4720 9660,4730 9580,4730 9540,4770 9160,4770 8760,4370 8270,4370 ; 7530,4350 7530,4390 ; 7530,4390 7530,4430 ; 7530,4430 7530,4480 ; 7530,4480 7640,4370 8270,4370
  Signal Layer 2 w25: J206.7@7530,4570 7530,4390 7673.62,4246.38 9233.62,4246.38 9426.05,4053.95 9506.05,4053.95 9530,4030 9530,3696.49 9580,3646.49 9580,2238.9 9530,2188.9 9530,2071 J204.4@9581,2020
BATT_RTN: J102.1 J102.2 J102.3 R102.1 R104.1 R108.1 R112.1 R116.1 R230.1 | length 909
  Top Layer w20: R230.1@10241.5,4480 v1(10290,4480) ; v1(10550,4260) R112.1@10550,4303.98
  Top Layer w50: R102.1@10366.4,4307.58 R112.1@10546.4,4307.58 R108.1@10636.4,4307.58 R104.1@10726.4,4307.58
  Signal Layer 1 w20: v1(10290,4480) 10350,4480 10520,4310 10520,4270 10530,4260 v1(10550,4260)
  Signal Layer 3 w20: v1(10550,4260) 10550,4281.99
  Signal Layer 4 w20: v1(10550,4260) 10550,4290
  Bottom Layer w20: v1(10550,4260) 10550,4290
  other v1: 11140,3960 11170,3980 10830,4100 10320,4370 10410,4370 10500,4370 10590,4370 10670,4370 10760,4370 10320,4440 11170,4510 11150,4540 10420,4550
COIL_PRI_N: C252.2 C253.1 pad.4 R261.1 R265.2 U211.3 | length 1064.9
  Signal Layer 1 w10: pad.4@3500,4430 3500,4704.72 3537.4,4742.13 3712.68,4742.13 3792.87,4822.32 3792.87,4912.87 v1(3830,4950)
  Bottom Layer w20: v1(3830,4950) C252.2@3830,4986.38 3835.59,4986.38 3857.4,5008.19 R265.2@3966.38,5008.19 U211.3@3966.38,5089.13 ; R261.1@3923.62,5100 U211.3@3966.38,5100
COIL_PRI_P: pad.3 R262.1 | length 895.4
  Signal Layer 1 w10: pad.3@3500,4350 3451.29,4398.71 3451.29,4681.29 3530,4760 3705.28,4760 3775,4829.72 3775,4945 v1(3780,4950)
  Bottom Layer w20: v1(3780,4950) R262.1@3780,4986.38
COIL_SEC_N: C248.2 C249.1 pad.2 R256.1 R259.2 U210.3 | length 379.7
  Top Layer w12: R256.1@3756.38,4350 3756.38,4402.76
  Top Layer w20: pad.2@3630,4430 3657.24,4402.76 3756.38,4402.76 C248.2@3756.38,4310 ; R259.2@3740,4406.38 3813.58,4406.38 U210.3@3829.8,4422.6
COIL_SEC_P: pad.1 R257.1 | length 159.5
  Top Layer w20: pad.1@3630,4350 3710,4270 R257.1@3756.38,4270
CS: Q104.2 Q105.2 R142.2 R143.2 R144.2 R145.2 R146.2 R213.2 | length 3063.1
  Top Layer w20: R213.2@1820,2956.38 1820,2910 1860,2870 1860,2520 v1(1880,2500) R144.2@1925.59,2500
  Top Layer w75: Q105.2@2700,1700 2320,1700 1970,2050 1970,2730 2086.93,2846.93 2226.93,2846.93 2630,3250 Q104.2@2710,3250
  Bottom Layer w20: v1(1880,2500) 1905.91,2500
  other v1: 2190,1660 1920,1920 1990,2280 1990,2320 1990,2360 1990,2400 1990,2440 1990,2480 1990,2520 1990,2560 1990,2600 1990,2640 1990,2680 1990,2720 1990,2780 2380,3270
G1H_P: D100.1 R118.1 TP204.1 | length 156.7
  Top Layer w25: TP204.1@2560,2810 R118.1@2658.5,2810 ; R118.1@2646.69,2821.81 D100.1@2646.69,2880
G1H_S: D102.1 R120.1 TP212.1 | length 176.9
  Top Layer w25: R120.1@9231.5,589.67 9379.67,589.67 TP212.1@9400,610
G1L_P: D104.1 R130.1 TP200.1 | length 136.7
  Top Layer w25: TP200.1@2570,3540 R130.1@2648.5,3540 ; R130.1@2636.69,3551.81 D104.1@2636.69,3610
G1L_S: D106.1 R132.1 TP208.1 | length 183.7
  Top Layer w25: R132.1@9231.5,1350 9244.8,1336.69 D106.1@9300,1336.69 9306.69,1336.69 9330,1360 TP208.1@9400,1360
G2H_P: D101.1 R119.1 TP205.1 | length 198.2
  Top Layer w25: TP205.1@2560,1280 2600,1240 D101.1@2666.69,1240 2678.5,1228.19 R119.1@2678.5,1170
G2H_S: D103.1 R121.1 TP213.1 | length 319.8
  Top Layer w25: D103.1@9184.67,2380 9184.67,2435.2 R121.1@9171.36,2448.5 9268.5,2448.5 9310,2490 TP213.1@9400,2490
G2L_P: D105.1 R131.1 TP201.1 | length 183.3
  Top Layer w25: TP201.1@2560,2020 2600,1980 R131.1@2658.5,1980 ; R131.1@2656.69,1981.81 D105.1@2656.69,2050
G2L_S: D107.1 R133.1 TP209.1 | length 170
  Top Layer w25: R133.1@9221.5,3231.46 TP209.1@9391.46,3231.46
HVBUS: C101.1 C102.1 C130.1 C131.1 Q100.1 Q101.1 R100.2 R101.2 R202.2 TP100.1 XF101.1 XF101.2 | length 9040.7
  Top Layer w20: v1(920,4270) 1210,4560 R202.2@1622.91,4560
  Signal Layer 1 w20: v1(920,4270) 920,2552.36 C102.1@1370,2102.36
  Bottom Layer w50: R101.2@1250,2086 1353.64,2086 C102.1@1370,2102.36
  Bottom Layer w75: Q101.1@2700,670 2840,670 2980,810 2980,2030 2780,2230 Q100.1@2710,2230
  Bottom Layer w100: XF101.1@760,353.46 908.03,501.5 1326.12,501.5 1373.49,548.87 1870,548.87 ; C102.1@1376.95,2095.41 1870,1602.36 1870,548.87 ; Q101.1@2700,680 2568.87,548.87 1870,548.87
  other v1: 2820,160 3070,420 3070,2200 3010,2260
ISNS_PRIM_SHUNT: R204.2 R212.1 R254.2 U200.1 | length 5978.2
  Top Layer w20: v1(1780,3140) 1784.8,3140 1787.4,3137.4 U200.1@1819.8,3137.4 ; R204.2@1970,2956.38 1976.38,2956.38 v1(2000,2980) ; R254.2@3916.38,4680 3916.38,4673.62 3920,4670 v1(3920,4630) ; v1(4119.1,5305.81) 4119.1,5219.52 R212.1@4131.5,5207.13
  Signal Layer 1 w20: v1@1787.4,3137.4 1787.87,3137.87 1882.13,3137.87 1930,3090 2020,3090 2037.87,3072.13 2037.87,3017.87 v1(2000,2980)
  Signal Layer 2 w20: v1(2000,2980) 1980,3000 1980,3190.58 2249.63,3460.21 2249.63,3990.84 2500,4241.21 v1(2500,4280) ; v1(3040,4312.13) 3062.13,4312.13 ; v1(3920,4630) 3780,4630 3710,4560 3352.79,4560 3104.92,4312.13 3062.13,4312.13 ; v1(4119.1,5305.81) 4339.27,5305.81 4348.45,5315 4421.55,5315 4437.87,5298.67 4437.87,5275.58 4376.55,5214.25 4194.25,5214.25 3976.38,4996.38 3506.38,4996.38 3230,4720 3230,4480 3062.13,4312.13
  Bottom Layer w20: v1(2500,4280) 2532.13,4312.13 v1(3040,4312.13)
ISNS_PRIM_TANK: C254.1 J202.23 J202.25 R264.1 | length 148.3
  Top Layer w20: v1(4060,4970) 4060,4993.07 J202.25@4046.02,5007.05 J202.23@4077.52,5007.05
  Bottom Layer w20: v1(4060,4970) R264.1@4060,5043.98
ISNS_REC_SEC: C208.1 R218.2 R225.2 U201.1 | length 329.1
  Top Layer w20: U201.1@3838.86,5377.88 R225.2@3958.26,5377.88 ; R218.2@3948.5,5207.13 3948.5,5256.66 3987.52,5295.67 3987.52,5349.85 R225.2@3951.62,5385.75
ISNS_SEC_TANK: C246.1 R229.1 R253.2 R255.2 U210.1 | length 693.2
  Top Layer w12: R255.2@3886.38,4371.65 v1@3886.38,4396.34
  Top Layer w20: R253.2@3816.38,4680 3816.38,4673.62 3820,4670 3820,4610 3829.8,4600.2 ; U210.1@3829.8,4497.4 3829.8,4600.2 ; C246.1@3886.38,4327.72 3886.38,4398.31 v1(3890,4401.93) ; R229.1@4016.38,4680 4016.38,4676.38 3940.2,4600.2 3829.8,4600.2
  Signal Layer 1 w20: v1(3830,4560) 3830,4461.93 v1(3890,4401.93)
NetC100_1: C100.1 C105.1 C108.1 C109.1 C110.1 C113.1 C114.1 C115.1 C116.1 C117.1 C118.1 C119.1 C120.1 C121.1 C123.1 C125.1 C127.1 C129.1 C135.1 C137.1 C139.1 C141.1 C147.1 C149.1 Q102.2 Q106.1 | length 363.1
  Top Layer w50: C116.1@8886.93,880 Q102.2@9250,880
  other v1: 8210,220 8900,220 8120,310 9080,410 8200,420 8250,420 8300,420 8350,420 8400,420 8450,420 8500,420 8550,420 8600,420 8650,420 8700,420 8120,440 8780,470 8860,560 8920,660 8920,710 8920,760 8920,810 8920,860 8920,910 8920,960 8920,1010 8920,1060 8920,1110 8920,1160 9120,1210 8820,1270 9050,1700 8820,1800 8980,1960
NetC100_2: C100.2 C105.2 C108.2 C109.2 C110.2 C113.2 C114.2 C115.2 C116.2 C117.2 C118.2 C119.2 C120.2 C121.2 C123.2 C125.2 C127.2 C129.2 C135.2 C137.2 C139.2 C141.2 C147.2 C149.2 J104.1 T100.4
NetC101_2: C101.2 C111.1 R105.1 R110.2 | length 723.3
  Top Layer w50: C101.2@1370,847.64 C111.1@1370,1312.36
  Bottom Layer w50: R105.1@1240,857.09 C101.2@1360.55,857.09 ; R110.2@1240,1292.91 1350.55,1292.91 C111.1@1370,1312.36
  other v1: 1180,920 1180,1000 1180,1170 1180,1300
NetC102_2: C102.2 C112.1 R106.1 R111.2 | length 718
  Top Layer w50: C102.2@1370,2397.64 C112.1@1370,2862.36
  Bottom Layer w50: R106.1@1250,2410.18 1357.46,2410.18 C102.2@1370,2397.64 ; R111.2@1250,2842.91 1350.55,2842.91 C112.1@1370,2862.36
